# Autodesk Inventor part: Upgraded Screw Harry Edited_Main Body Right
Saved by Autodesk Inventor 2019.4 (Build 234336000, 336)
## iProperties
Created: 2020-06
Part Number: Upgraded Screw Harry Edited_Main Body Right
Material: Generic
Document SubType Name: Modeling
Designer: Administrator
Density: 1 g/cm^3
Appearance: Default
Title: Upgraded Screw Harry Edited_Main Body Right v2
Author: Administrator
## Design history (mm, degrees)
feature "Main Body (2)"
body "Solid1"
